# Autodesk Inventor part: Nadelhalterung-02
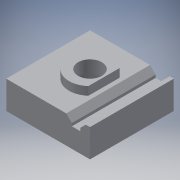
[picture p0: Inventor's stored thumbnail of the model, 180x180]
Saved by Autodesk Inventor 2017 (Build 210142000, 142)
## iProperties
Company: VDW-Nachwuchsstiftung
Created: 2014-04
Part Number: Nadelhalterung-02
Material: Aluminium 6061
Document SubType Name: Modeling
Designer: e_dammj
Density: 2.71 g/cm^3
Appearance: Aluminium - flach
Project: Verstellbarer Werkstückanschlag
Mass: 24.5784 g
Surface Area: 36.3222 cm^2
Volume: 9.06953 cm^3
Author: e_dammj
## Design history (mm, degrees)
sketch "Skizze1"
  geometry: L1 (-15, 15)-(15, 15); L2 (15, 15)-(15, -15); L3 (15, -15)-(-15, -15); L4 (-15, -15)-(-15, 15); L5 (-15, 15)-(15, -15); L6 (15, 15)-(-15, -15); 1 further point
  constraints: 12 end point, 2 midpoint, 2 parallel, 1 horizontal, 1 perpendicular
  dimensions: "d0" = 30 distance of L2.end L3.end; "d1" = 30 distance of L1.end L2.end
extrude "Grundkörper" new body sketch "Skizze1" distance "d2" = 10; taper "d3" = 0 deg
sketch "Skizze2"
  geometry: C1 r 7.5 at (0, 0); 1 further point
  constraints: 1 centre point, 1 coincident
  dimensions: "d4" = 15 diameter of C1
extrude "Ansatz D=15" join sketch "Skizze2" distance "d5" = 3; taper "d6" = 0 deg
sketch "Skizze3"
  geometry: 2 further points
  constraints: 1 coincident
hole "Senkbohrung" sketch "Skizze3" at (0, 0) diameter "d7" = 8.5; stored, may be unused: countersink angle "d11" = 90 deg, drill point angle "d13" = 118 deg; dims "d8" = 6, "d9" = 13.5, "d10" = 8.5, "d12" = 8
sketch "Skizze4"
  geometry: L1 (30, 0)-(0, 0) reference; L2 (0, 0)-(0, 10) reference; L3 (28.5, 0)-(26.5, 2); L4 (26.5, 2)-(26.5, 3); L5 (25, 4.983)-(25, -1.414); L6 (26.5, 3)-(25, 3); L7 (15, -2.352)-(15, 14.525); L8 (21.5, 0)-(23.5, 2); L9 (23.5, 2)-(23.5, 3); L10 (23.5, 3)-(25, 3); L11 (25, 0)-(28.5, 0); L12 (25, 0)-(21.5, 0); L13 (30, 0)-(30, 10) reference; L14 (-0.651, 5)-(31.282, 5); L15 (21.5, 10)-(23.5, 8); L16 (23.5, 8)-(23.5, 7); L17 (25, 10)-(21.5, 10); L18 (23.5, 7)-(25, 7); L19 (26.5, 8)-(26.5, 7); L20 (26.5, 7)-(25, 7); L21 (28.5, 10)-(26.5, 8); L22 (25, 10)-(28.5, 10); L23 (22.5, 13)-(7.5, 13) reference; L24 (22.5, 13)-(7.5, 13) reference; L25 (7.5, 10)-(22.5, 10) reference; L26 (7.5, 10)-(7.5, 13) reference; L27 (22.5, 10)-(22.5, 13) reference; L28 (22.5, 10)-(20, 10); L29 (20, 10)-(20, 13); L30 (20, 13)-(22.5, 13); L31 (22.5, 13)-(22.5, 10); 4 further points
  constraints: 46 end point, 12 symmetric about line, 7 point on line, 4 perpendicular, 3 parallel, 2 collinear, 2 midpoint, 1 horizontal
  dimensions: "d15" = 3 diameter of L4 L5; "d16" = 10 distance between parallel lines of L7 L5; "d17" = 1 distance from line of L3.end L6; "d18" = 3 distance from line of L6 L3.start; "d19" = 45 deg angle of L5 L3; "d24" = 12.5 distance between parallel lines of L26 L29
  node "Projizierte Kontur1"
extrude "Nut Unterteil" cut sketch "Skizze4" stored distance "d20" = 1.5; taper "d21" = 0 deg
extrude "Nut Oberteil" cut sketch "Skizze4" stored distance "d22" = 1.5; taper "d23" = 0 deg
node "Volumenkörper1"
